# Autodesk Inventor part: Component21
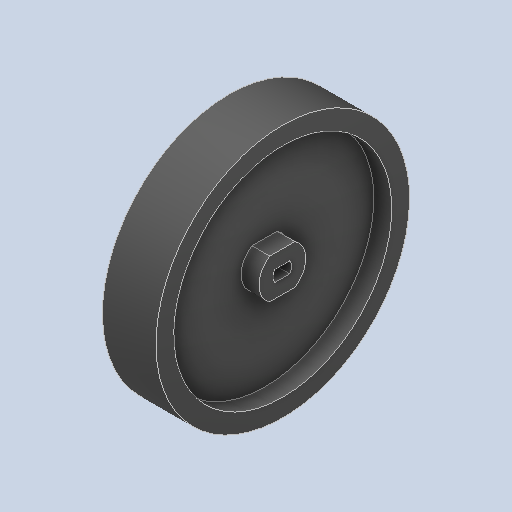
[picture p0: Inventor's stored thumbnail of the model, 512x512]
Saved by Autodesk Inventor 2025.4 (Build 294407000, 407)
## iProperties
Created: 2026-06
Part Number: Component21
Material: Generic
Document SubType Name: Modeling
Designer: AdminForWorker
Density: 1 g/cm^3
Appearance: Default
Title: Component21
Author: AdminForWorker
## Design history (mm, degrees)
feature "Body1"
body "Solid1"
